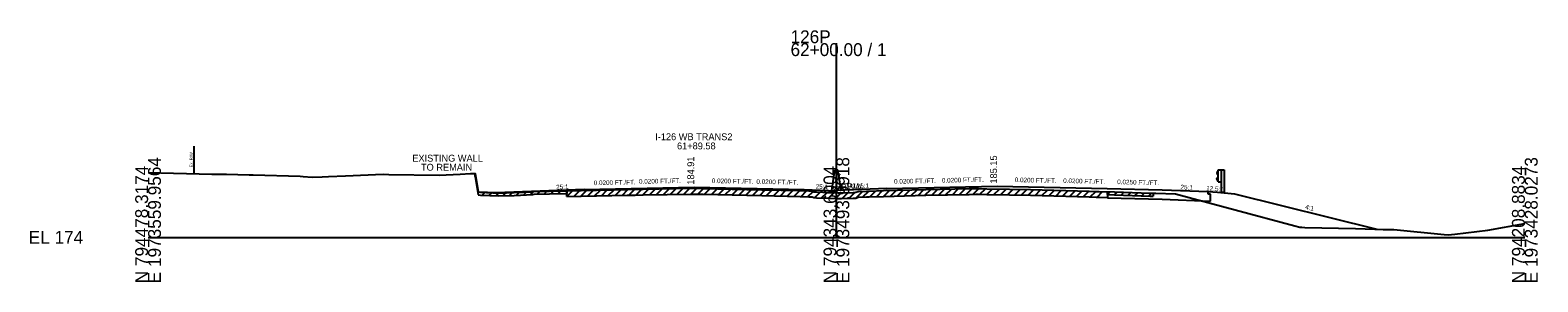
# Model space of a CAD drawing. Extents: x -161 to 1970889, y -4362 to 797231.
# Drawn here: x 1974.3 to 2302.8, y 9490.3 to 9545.1 of the extents above; entities that cross this region are included whole.
import ezdxf

# ---------------------------------------------------------------- set-up
doc = ezdxf.new("R2010")
doc.units = 0
for name, color, linetype in [('RD_GPK_XS_Cell', 7, 'Continuous'), ('RD_XS_Base', 7, 'Continuous'), ('RD_XS_EarthShd', 7, 'Continuous'), ('RD_XS_ExGround', 7, 'Continuous'), ('RD_XS_ExPaveRet', 7, 'Continuous'), ('RD_XS_ExRW', 7, 'Continuous'), ('RD_XS_GR', 7, 'Continuous'), ('RD_XS_MedBWall', 7, 'Continuous'), ('RD_XS_Misc_Line', 7, 'Continuous'), ('RD_XS_Pave', 7, 'Continuous'), ('RD_XS_PaveOvlay', 7, 'Continuous'), ('RD_XS_PaveShd', 7, 'Continuous'), ('RD_XS_TieSlope', 7, 'Continuous'), ('RD_XS_TX_Elev_EX', 7, 'Continuous'), ('RD_XS_TX_Elev_PR', 7, 'Continuous'), ('RD_XS_TX_MkPT', 7, 'Continuous'), ('RD_XS_TX_Notes', 7, 'Continuous'), ('RD_XS_TX_Profile', 7, 'Continuous'), ('RD_XS_TX_ShdSlope', 7, 'Continuous'), ('RD_XS_TX_Slope', 7, 'Continuous'), ('RD_XS_TX_Station', 7, 'Continuous')]:
    doc.layers.add(name, color=color, linetype=linetype)

msp = doc.modelspace()

# ---------------------------------------------------------------- linework, layer by layer
at = {"layer": 'RD_GPK_XS_Cell'}
for p, q in [((2150, 9500), (2150, 9542.29)), ((2000, 9500), (2150, 9500)), ((2150, 9500), (2300, 9500))]:
    msp.add_line(p, q, dxfattribs=at)
at = {"layer": 'RD_XS_Base'}
for p, q in [((2209.05, 9508.63), (2221, 9508.33)), ((2221, 9508.33), (2231.5, 9507.91)), ((2231, 9509.41), (2231, 9509.97)), ((2231.5, 9509.39), (2231, 9509.41)), ((2231.5, 9507.91), (2231.5, 9509.39))]:
    msp.add_line(p, q, dxfattribs=at)
at = {"layer": 'RD_XS_EarthShd'}
msp.add_line((2231, 9509.97), (2233, 9509.81), dxfattribs=at)
at = {"layer": 'RD_XS_ExGround'}
msp.add_lwpolyline([(2000, 9514.1), (2013.91, 9513.79), (2015.24, 9513.76), (2015.75, 9513.75), (2017.08, 9513.73), (2022.05, 9513.64), (2022.87, 9513.61), (2033.15, 9513.3), (2033.79, 9513.27), (2035.77, 9513.14), (2037.97, 9513.19), (2039.35, 9513.22), (2043.03, 9513.4), (2051.23, 9513.74), (2052.44, 9513.72), (2063.4, 9513.52), (2068, 9513.76), (2070.27, 9513.89), (2071.28, 9513.89), (2071.9, 9509.88), (2072.41, 9509.85), (2076.47, 9509.64), (2079.75, 9509.77), (2083.83, 9509.93), (2084.12, 9510.04), (2087.49, 9510.08), (2094.34, 9510.2), (2104.4, 9510.42), (2106.14, 9510.46), (2107.92, 9510.49), (2118.32, 9510.69), (2120.95, 9510.64), (2130.44, 9510.45), (2133.72, 9510.38), (2142.08, 9510.18), (2143.96, 9510.11), (2144.68, 9510.08), (2145.08, 9509.92), (2145.62, 9509.89), (2148.35, 9509.76), (2150, 9509.74), (2151.08, 9509.72), (2153.61, 9509.8), (2154.23, 9509.82), (2154.74, 9510), (2156.52, 9510.07), (2157.1, 9510.09), (2160.27, 9510.18), (2169.45, 9510.42), (2178.9, 9510.61), (2180.38, 9510.65), (2180.97, 9510.64), (2182.76, 9510.58), (2187.68, 9510.5), (2192.26, 9510.41), (2205.04, 9510.05), (2206.61, 9510), (2207.24, 9509.98), (2210.59, 9509.88), (2218.39, 9509.63), (2219.05, 9509.6), (2219.58, 9509.59), (2223.86, 9509.46), (2249.86, 9502.51), (2250.97, 9502.21), (2251.41, 9502.2), (2252.04, 9502.18), (2263.12, 9501.92), (2267.34, 9501.78), (2269.13, 9501.73), (2271.48, 9501.69), (2282.41, 9500.64), (2283.27, 9500.57), (2284.78, 9500.68), (2291.97, 9501.54), (2300, 9503.01)], dxfattribs=at)
at = {"layer": 'RD_XS_ExPaveRet'}
for p, q in [((2071.28, 9513.27), (2071.28, 9513.89)), ((2071.28, 9513.27), (2071.9, 9509.25)), ((2071.9, 9509.25), (2072.41, 9509.22)), ((2072.41, 9509.22), (2076.47, 9509.01)), ((2076.47, 9509.01), (2079.75, 9509.14)), ((2079.75, 9509.14), (2083.83, 9509.31)), ((2083.83, 9509.31), (2084.12, 9509.41)), ((2084.12, 9509.41), (2087.49, 9509.46)), ((2087.49, 9509.46), (2091.28, 9509.52)), ((2091.28, 9508.9), (2091.28, 9510.15)), ((2091.28, 9510.15), (2091.28, 9509.52)), ((2091.28, 9508.9), (2094.34, 9508.95)), ((2094.34, 9508.95), (2104.4, 9509.17)), ((2104.4, 9509.17), (2106.14, 9509.21)), ((2106.14, 9509.21), (2107.92, 9509.24)), ((2107.92, 9509.24), (2118.32, 9509.44)), ((2118.32, 9509.44), (2120.95, 9509.39)), ((2120.95, 9509.39), (2130.44, 9509.2)), ((2130.44, 9509.2), (2133.72, 9509.13)), ((2133.72, 9509.13), (2142.08, 9508.93)), ((2142.08, 9508.93), (2143.96, 9508.86)), ((2143.96, 9508.86), (2144.68, 9508.83)), ((2144.68, 9508.83), (2145.08, 9508.67)), ((2145.08, 9508.67), (2145.62, 9508.64)), ((2145.62, 9508.64), (2148.35, 9508.51)), ((2148.35, 9508.51), (2150, 9508.49)), ((2150, 9508.49), (2151.08, 9508.47)), ((2151.08, 9508.47), (2153.61, 9508.55)), ((2153.61, 9508.55), (2154.23, 9508.57)), ((2154.23, 9508.57), (2154.74, 9508.75)), ((2154.74, 9508.75), (2156.52, 9508.82)), ((2156.52, 9508.82), (2157.1, 9508.84)), ((2157.1, 9508.84), (2160.27, 9508.93)), ((2160.27, 9508.93), (2169.45, 9509.17)), ((2169.45, 9509.17), (2178.9, 9509.36)), ((2178.9, 9509.36), (2180.38, 9509.4)), ((2180.38, 9509.4), (2180.97, 9509.39)), ((2180.97, 9509.39), (2182.76, 9509.33)), ((2182.76, 9509.33), (2187.68, 9509.25)), ((2187.68, 9509.25), (2192.26, 9509.16)), ((2192.26, 9509.16), (2205.04, 9508.8)), ((2205.04, 9508.8), (2206.61, 9508.75)), ((2206.61, 9508.75), (2207.24, 9508.73)), ((2207.24, 9508.73), (2209.05, 9508.68)), ((2209.05, 9509.93), (2209.05, 9508.68)), ((2209.05, 9509.3), (2209.05, 9509.93)), ((2209.05, 9509.3), (2210.59, 9509.25)), ((2210.59, 9509.25), (2218.39, 9509)), ((2218.39, 9509), (2219.05, 9508.98)), ((2219.05, 9509.6), (2219.05, 9508.98))]:
    msp.add_line(p, q, dxfattribs=at)
at = {"layer": 'RD_XS_ExRW'}
msp.add_line((2010, 9519.88), (2010, 9513.88), dxfattribs=at)
at = {"layer": 'RD_XS_GR'}
for p, q in [((2233.15, 9514.52), (2232.88, 9514.08)), ((2233.15, 9514.68), (2233.81, 9514.68)), ((2233.15, 9512.11), (2233.15, 9514.68)), ((2233.81, 9514.68), (2234.48, 9514.68)), ((2233.81, 9514.68), (2233.81, 9509.74)), ((2234.48, 9514.68), (2234.48, 9509.63)), ((2232.88, 9514.08), (2232.88, 9513.97)), ((2232.88, 9513.97), (2233.15, 9513.53)), ((2232.88, 9512.82), (2233.15, 9513.26)), ((2232.88, 9512.71), (2232.88, 9512.82)), ((2233.15, 9512.27), (2232.88, 9512.71)), ((2233.15, 9512.11), (2233.81, 9512.11))]:
    msp.add_line(p, q, dxfattribs=at)
at = {"layer": 'RD_XS_MedBWall'}
for p, q in [((2149, 9510.17), (2149.67, 9514.65)), ((2149.67, 9514.73), (2150.33, 9514.73)), ((2149.67, 9514.65), (2149.67, 9514.73)), ((2150, 9514.73), (2150.33, 9514.73)), ((2151, 9510.25), (2150.33, 9514.73))]:
    msp.add_line(p, q, dxfattribs=at)
at = {"layer": 'RD_XS_Misc_Line'}
for p, q in [((2071.28, 9513.27), (2071.37, 9513.35)), ((2072.78, 9509.2), (2073.38, 9509.8)), ((2074.28, 9509.13), (2074.88, 9509.72)), ((2075.78, 9509.05), (2076.38, 9509.64)), ((2077.28, 9509.04), (2077.93, 9509.69)), ((2078.78, 9509.1), (2079.43, 9509.75)), ((2080.28, 9509.16), (2080.93, 9509.81)), ((2081.78, 9509.22), (2082.43, 9509.88)), ((2083.28, 9509.29), (2083.99, 9509.99)), ((2084.78, 9509.42), (2085.42, 9510.05)), ((2086.28, 9509.44), (2086.92, 9510.08)), ((2087.78, 9509.46), (2088.42, 9510.1)), ((2089.28, 9509.49), (2089.92, 9510.12)), ((2091.28, 9508.9), (2092.55, 9510.17)), ((2092.78, 9508.92), (2094.05, 9510.19)), ((2094.28, 9508.95), (2095.56, 9510.23)), ((2095.78, 9508.98), (2097.06, 9510.26)), ((2097.28, 9509.01), (2098.56, 9510.29)), ((2098.78, 9509.05), (2100.06, 9510.33)), ((2100.28, 9509.08), (2101.56, 9510.36)), ((2101.78, 9509.11), (2103.06, 9510.39)), ((2103.28, 9509.15), (2104.56, 9510.43)), ((2104.78, 9509.18), (2106.06, 9510.46)), ((2106.28, 9509.21), (2107.56, 9510.49)), ((2107.78, 9509.24), (2109.06, 9510.52)), ((2109.28, 9509.27), (2110.56, 9510.54)), ((2110.78, 9509.3), (2112.06, 9510.57)), ((2112.28, 9509.33), (2113.56, 9510.6)), ((2113.78, 9509.36), (2115.06, 9510.63)), ((2115.28, 9509.39), (2116.56, 9510.66)), ((2116.78, 9509.41), (2118.06, 9510.69)), ((2118.28, 9509.44), (2119.51, 9510.67)), ((2119.78, 9509.42), (2121.01, 9510.64)), ((2121.28, 9509.39), (2122.51, 9510.61)), ((2122.78, 9509.36), (2124.01, 9510.58)), ((2124.28, 9509.33), (2125.51, 9510.55)), ((2125.78, 9509.3), (2127.01, 9510.52)), ((2127.28, 9509.27), (2128.51, 9510.49)), ((2128.78, 9509.24), (2130.01, 9510.46)), ((2130.28, 9509.21), (2131.5, 9510.43)), ((2131.78, 9509.17), (2133, 9510.4)), ((2133.28, 9509.14), (2134.5, 9510.36)), ((2134.78, 9509.1), (2136, 9510.32)), ((2136.28, 9509.07), (2137.5, 9510.29)), ((2137.78, 9509.03), (2139, 9510.25)), ((2139.28, 9509), (2140.5, 9510.22)), ((2140.78, 9508.96), (2142, 9510.18)), ((2142.28, 9508.93), (2143.49, 9510.13)), ((2143.78, 9508.87), (2144.9, 9509.99)), ((2145.28, 9508.66), (2146.47, 9509.85)), ((2146.78, 9508.59), (2147.97, 9509.78)), ((2148.28, 9508.51), (2149.51, 9509.74)), ((2149.78, 9508.49), (2151.02, 9509.72)), ((2151.28, 9508.48), (2152.57, 9509.77)), ((2152.78, 9508.52), (2154.07, 9509.81)), ((2154.28, 9508.58), (2155.74, 9510.04)), ((2155.78, 9508.79), (2157.09, 9510.09)), ((2157.28, 9508.85), (2158.57, 9510.13)), ((2158.78, 9508.89), (2160.07, 9510.17)), ((2160.28, 9508.93), (2161.57, 9510.21)), ((2161.78, 9508.97), (2163.07, 9510.25)), ((2163.28, 9509.01), (2164.57, 9510.29)), ((2164.78, 9509.05), (2166.07, 9510.33)), ((2166.28, 9509.08), (2167.57, 9510.37)), ((2167.78, 9509.12), (2169.07, 9510.41)), ((2169.28, 9509.16), (2170.56, 9510.44)), ((2170.78, 9509.2), (2172.06, 9510.47)), ((2172.28, 9509.23), (2173.56, 9510.5)), ((2173.78, 9509.26), (2175.06, 9510.53)), ((2175.28, 9509.29), (2176.56, 9510.56)), ((2176.78, 9509.32), (2178.06, 9510.6)), ((2178.28, 9509.35), (2179.56, 9510.63)), ((2179.78, 9509.39), (2181.03, 9510.64)), ((2181.28, 9509.38), (2182.5, 9510.59)), ((2182.78, 9509.33), (2184.01, 9510.56)), ((2184.28, 9509.31), (2185.51, 9510.53)), ((2185.78, 9509.28), (2187.01, 9510.51)), ((2187.28, 9509.25), (2188.51, 9510.48)), ((2188.78, 9509.22), (2190.01, 9510.45)), ((2190.28, 9509.19), (2191.51, 9510.42)), ((2191.78, 9509.17), (2193, 9510.39)), ((2193.28, 9509.13), (2194.5, 9510.34)), ((2194.78, 9509.09), (2196, 9510.3)), ((2196.28, 9509.04), (2197.5, 9510.26)), ((2197.78, 9509), (2199, 9510.22)), ((2199.28, 9508.96), (2200.5, 9510.17)), ((2200.78, 9508.92), (2202, 9510.13)), ((2202.28, 9508.87), (2203.5, 9510.09)), ((2203.78, 9508.83), (2205, 9510.05)), ((2205.28, 9508.79), (2206.5, 9510.01)), ((2206.78, 9508.75), (2208, 9509.96)), ((2209.05, 9509.3), (2209.65, 9509.91)), ((2210.55, 9509.25), (2211.15, 9509.86)), ((2212.05, 9509.2), (2212.65, 9509.81)), ((2213.55, 9509.16), (2214.15, 9509.76)), ((2215.05, 9509.11), (2215.65, 9509.71)), ((2216.55, 9509.06), (2217.15, 9509.67)), ((2218.05, 9509.01), (2218.65, 9509.62))]:
    msp.add_line(p, q, dxfattribs=at)
at = {"layer": 'RD_XS_Pave'}
for p, q in [((2161, 9510.67), (2185, 9511.15)), ((2185, 9511.15), (2209, 9510.67)), ((2095, 9510.43), (2119, 9510.91)), ((2119, 9510.91), (2143, 9510.43)), ((2209, 9510.67), (2221, 9510.37))]:
    msp.add_line(p, q, dxfattribs=at)
at = {"layer": 'RD_XS_PaveOvlay'}
for p, q in [((2091.28, 9510.15), (2094.34, 9510.2)), ((2094.34, 9510.2), (2104.4, 9510.42)), ((2104.4, 9510.42), (2106.14, 9510.46)), ((2106.14, 9510.46), (2107.92, 9510.49)), ((2107.92, 9510.49), (2118.32, 9510.69)), ((2118.32, 9510.69), (2120.95, 9510.64)), ((2120.95, 9510.64), (2130.44, 9510.45)), ((2130.44, 9510.45), (2133.72, 9510.38)), ((2133.72, 9510.38), (2142.08, 9510.18)), ((2142.08, 9510.18), (2143.96, 9510.11)), ((2143.96, 9510.11), (2144.68, 9510.08)), ((2144.68, 9510.08), (2145.08, 9509.92)), ((2145.08, 9509.92), (2145.62, 9509.89)), ((2145.62, 9509.89), (2148.35, 9509.76)), ((2148.35, 9509.76), (2150, 9509.74)), ((2150, 9509.74), (2151.08, 9509.72)), ((2151.08, 9509.72), (2153.61, 9509.8)), ((2153.61, 9509.8), (2154.23, 9509.82)), ((2154.23, 9509.82), (2154.74, 9510)), ((2154.74, 9510), (2156.52, 9510.07)), ((2156.52, 9510.07), (2157.1, 9510.09)), ((2157.1, 9510.09), (2160.27, 9510.18)), ((2160.27, 9510.18), (2169.45, 9510.42)), ((2169.45, 9510.42), (2178.9, 9510.61)), ((2178.9, 9510.61), (2180.38, 9510.65)), ((2180.38, 9510.65), (2180.97, 9510.64)), ((2180.97, 9510.64), (2182.76, 9510.58)), ((2182.76, 9510.58), (2187.68, 9510.5)), ((2187.68, 9510.5), (2192.26, 9510.41)), ((2192.26, 9510.41), (2205.04, 9510.05)), ((2205.04, 9510.05), (2206.61, 9510)), ((2206.61, 9510), (2207.24, 9509.98)), ((2207.24, 9509.98), (2209.05, 9509.93)), ((2209.05, 9509.93), (2209.05, 9508.63))]:
    msp.add_line(p, q, dxfattribs=at)
msp.add_lwpolyline([(2075.85, 9509.67), (2076.47, 9509.64), (2079.75, 9509.77), (2083.83, 9509.93), (2084.12, 9510.04), (2087.49, 9510.08), (2091.28, 9510.15)], dxfattribs=at)
at = {"layer": 'RD_XS_PaveShd'}
for p, q in [((2075.85, 9509.67), (2072.15, 9509.86)), ((2095, 9510.43), (2075.85, 9509.67)), ((2143, 9510.43), (2150, 9510.15)), ((2161, 9510.67), (2150, 9510.23)), ((2150, 9510.15), (2150, 9510.23)), ((2221, 9510.37), (2231, 9509.97))]:
    msp.add_line(p, q, dxfattribs=at)
at = {"layer": 'RD_XS_TieSlope'}
for p, q in [((2233, 9509.81), (2236.75, 9509.51)), ((2236.75, 9509.51), (2267.73, 9501.77))]:
    msp.add_line(p, q, dxfattribs=at)

# ---------------------------------------------------------------- texts
at = {"layer": 'RD_GPK_XS_Cell'}
for s, p in [('126P', (2140, 9542.29)), ('62+00.00 / 1', (2140, 9539.49)), ('EL 174', (1974, 9498.6))]:
    msp.add_text(s, height=2.8, dxfattribs=at).set_placement(p)
for s, p in [('N 794478.3174', (2000, 9490)), ('E 1973559.9564', (2002.8, 9490)), ('N 794343.6004', (2150, 9490)), ('E 1973493.9918', (2152.8, 9490)), ('N 794208.8834', (2300, 9490)), ('E 1973428.0273', (2302.8, 9490))]:
    msp.add_text(s, height=2.8, rotation=90, dxfattribs=at).set_placement(p)
at = {"layer": 'RD_XS_ExRW'}
msp.add_text('Ex. R/W ', height=0.65, rotation=90, dxfattribs=at).set_placement((2009.75, 9515.26))
at = {"layer": 'RD_XS_TX_Elev_EX'}
msp.add_text('183.74', height=1, rotation=90, dxfattribs=at).set_placement((2151, 9509.74))
at = {"layer": 'RD_XS_TX_Elev_PR'}
for s, p in [(' 185.15', (2185, 9511.15)), (' 184.91', (2119, 9510.91))]:
    msp.add_text(s, height=1.5, rotation=90, dxfattribs=at).set_placement(p)
at = {"layer": 'RD_XS_TX_MkPT'}
for s, p in [('WBW', (2149, 9510.17)), ('EBW', (2151, 9510.25))]:
    msp.add_text(s, height=1.5, dxfattribs=at).set_placement(p)
at = {"layer": 'RD_XS_TX_Notes'}
for s, p in [('EXISTING WALL', (2057.58, 9516.49)), ('TO REMAIN', (2059.47, 9514.52))]:
    msp.add_text(s, height=1.5, dxfattribs=at).set_placement(p)
at = {"layer": 'RD_XS_TX_Profile'}
for rotation, p in [(2.2906, (2088.94, 9510.44)), (357.7094, (2145.46, 9510.59)), (2.2906, (2154.44, 9510.65)), (357.7094, (2224.96, 9510.46))]:
    msp.add_text('25:1', height=1, rotation=rotation, dxfattribs=at).set_placement(p)
at = {"layer": 'RD_XS_TX_ShdSlope'}
msp.add_text('12.5:1', height=1, rotation=355.4261, dxfattribs=at).set_placement((2230.54, 9510.25))
at = {"layer": 'RD_XS_TX_Slope'}
for s, rotation, p in [('0.0200 FT./FT.', 1.1458, (2097.12, 9511.36)), ('0.0200 FT./FT.', 1.1458, (2106.98, 9511.67)), ('0.0200 FT./FT.', 358.8542, (2122.83, 9511.84)), ('0.0200 FT./FT.', 358.8542, (2132.55, 9511.66)), ('0.0200 FT./FT.', 1.1458, (2162.56, 9511.67)), ('0.0200 FT./FT.', 1.1458, (2172.98, 9511.91)), ('0.0200 FT./FT.', 358.569, (2188.84, 9512.05)), ('0.0200 FT./FT.', 358.569, (2199.4, 9511.86)), ('0.0250 FT./FT.', 358.5679, (2211.17, 9511.6)), ('4:1', 345.9638, (2252.07, 9506.2))]:
    msp.add_text(s, height=1, rotation=rotation, dxfattribs=at).set_placement(p)
at = {"layer": 'RD_XS_TX_Station'}
for s, p in [('I-126 WB TRANS2', (2110.51, 9521.16)), ('61+89.58', (2115.26, 9519.16))]:
    msp.add_text(s, height=1.5, dxfattribs=at).set_placement(p)

doc.saveas('drawing.dxf')
